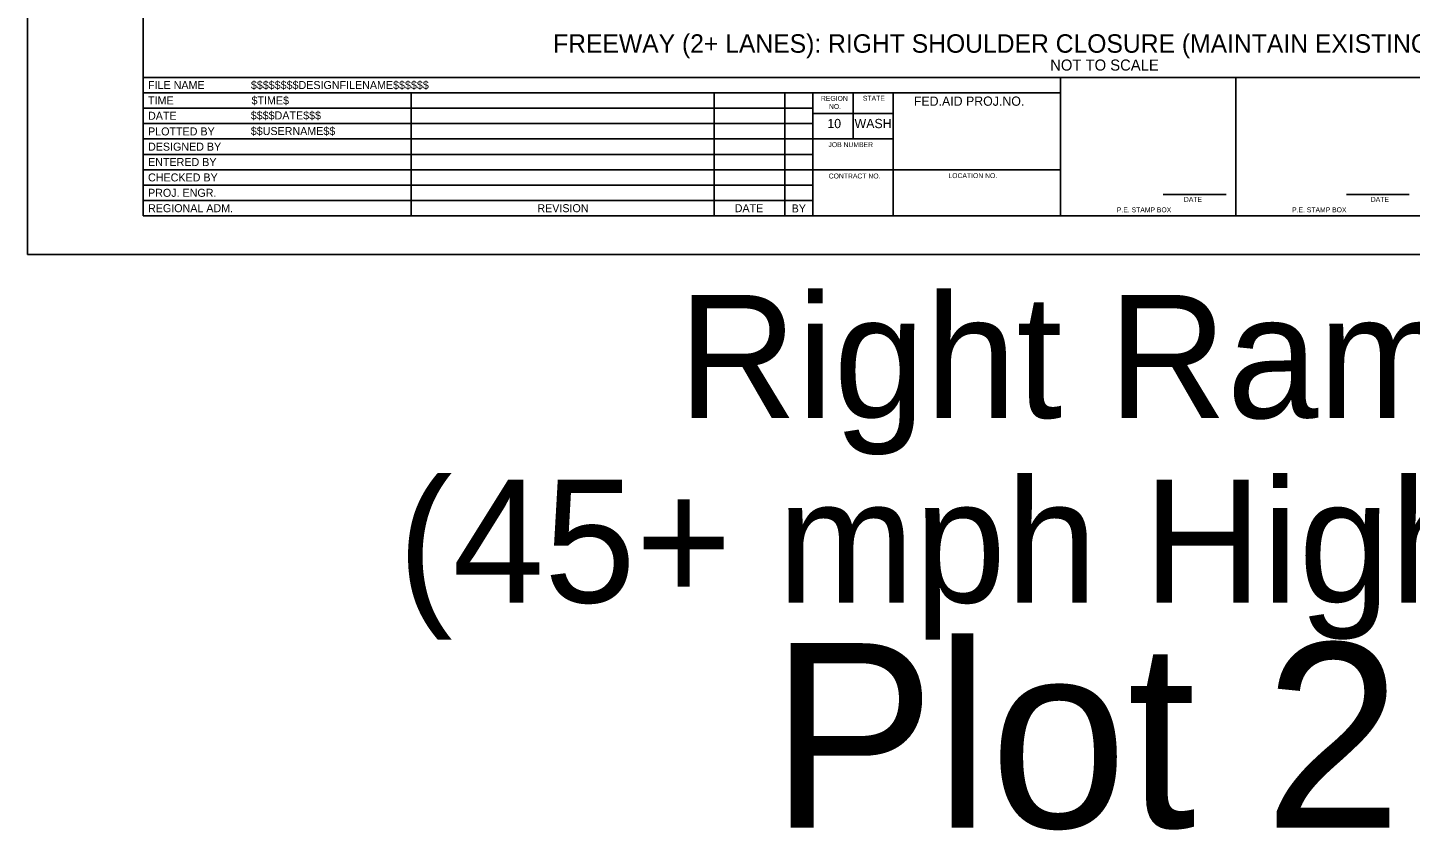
# Model space of a CAD drawing. Extents: x 99999.1 to 100055.7, y 99995 to 100013.2.
# Drawn here: x 100019.06 to 100030.3, y 99995.01 to 100001.53 of the extents above; entities that cross this region are included whole.
import ezdxf

# ---------------------------------------------------------------- set-up
doc = ezdxf.new("R2010")
doc.units = 0
for name, color, linetype in [('SH_DE_DetailHeading1Text', 7, 'Continuous'), ('SH_GI_PlotLimits', 7, 'Continuous'), ('SH_GI_SheetBorder', 7, 'Continuous'), ('SH_GI_SheetLocationText', 7, 'Continuous'), ('SH_GI_SheetTextInCells', 7, 'Continuous'), ('SH_GI_TitleBlockText', 7, 'Continuous')]:
    doc.layers.add(name, color=color, linetype=linetype)

msp = doc.modelspace()

# ---------------------------------------------------------------- linework, layer by layer
at = {"layer": 'SH_GI_PlotLimits'}
msp.add_lwpolyline([(100019.062, 99999.687), (100036.062, 99999.687), (100036.062, 100010.687), (100019.062, 100010.687)], close=True, dxfattribs=at)
at = {"layer": 'SH_GI_SheetBorder'}
for p, q in [((100020, 100010.375), (100020, 100000)), ((100020, 100001.126), (100035.75, 100001.126)), ((100027.457, 100000), (100027.457, 100001.126)), ((100028.883, 100000), (100028.883, 100001.126)), ((100020, 100001.001), (100027.457, 100001.001)), ((100022.179, 100001.001), (100022.179, 100000)), ((100024.641, 100001.001), (100024.641, 100000)), ((100025.216, 100001.001), (100025.216, 100000)), ((100025.445, 100001.001), (100025.445, 100000)), ((100025.772, 100000.625), (100025.772, 100001.001)), ((100026.096, 100000), (100026.096, 100001.001)), ((100020, 100000.876), (100022.182, 100000.876)), ((100022.182, 100000.876), (100025.447, 100000.876)), ((100026.096, 100000.831), (100025.447, 100000.831)), ((100020, 100000.751), (100022.182, 100000.751)), ((100022.182, 100000.751), (100025.447, 100000.751)), ((100020, 100000.625), (100025.447, 100000.625)), ((100026.096, 100000.625), (100025.447, 100000.625)), ((100020, 100000.5), (100025.447, 100000.5)), ((100020, 100000.375), (100025.447, 100000.375)), ((100027.457, 100000.375), (100025.447, 100000.375)), ((100020, 100000.25), (100025.447, 100000.25)), ((100020, 100000.125), (100025.447, 100000.125)), ((100028.29, 100000.173), (100028.802, 100000.173)), ((100029.78, 100000.173), (100030.291, 100000.173)), ((100020, 100000), (100035.75, 100000))]:
    msp.add_line(p, q, dxfattribs=at)

# ---------------------------------------------------------------- texts
at = {"layer": 'SH_DE_DetailHeading1Text'}
for s, height, p in [('FREEWAY (2+ LANES): RIGHT SHOULDER CLOSURE (MAINTAIN EXISTING SPEED LIMIT)', 0.15, (100023.333, 100001.326)), ('NOT TO SCALE', 0.09, (100027.373, 100001.181))]:
    msp.add_text(s, height=height, rotation=360, dxfattribs=at).set_placement(p)
at = {"layer": 'SH_GI_SheetLocationText'}
for s, height, p in [('Right Ramps', 1, (100024.35, 99998.357)), ('(45+ mph Highways)', 1, (100022.071, 99996.857)), ('Plot 2', 1.5, (100025.1, 99995.027))]:
    msp.add_text(s, height=height, dxfattribs=at).set_placement(p)
at = {"layer": 'SH_GI_SheetTextInCells'}
for s, height, p in [('FILE NAME', 0.0651, (100020.041, 100001.031)), ('TIME', 0.0651, (100020.041, 100000.906)), ('REGION', 0.04, (100025.51, 100000.935)), ('NO.', 0.04, (100025.575, 100000.869)), ('STATE', 0.04, (100025.851, 100000.936)), ('FED.AID PROJ.NO.', 0.07506, (100026.265, 100000.895)), ('DATE', 0.0651, (100020.041, 100000.781)), ('10', 0.0751, (100025.562, 100000.713)), ('WASH', 0.0751, (100025.783, 100000.713)), ('PLOTTED BY', 0.0651, (100020.041, 100000.654)), ('DESIGNED BY', 0.06505, (100020.041, 100000.53)), ('JOB NUMBER', 0.04, (100025.571, 100000.559)), ('ENTERED BY', 0.0651, (100020.041, 100000.405)), ('CHECKED BY', 0.0651, (100020.041, 100000.28)), ('CONTRACT NO.', 0.04003, (100025.573, 100000.304)), ('LOCATION NO.', 0.04003, (100026.546, 100000.307)), ('PROJ. ENGR.', 0.06505, (100020.041, 100000.155)), ('DATE', 0.04, (100028.46, 100000.114)), ('DATE', 0.04, (100029.979, 100000.114)), ('REGIONAL ADM.', 0.06505, (100020.041, 100000.03)), ('REVISION', 0.0651, (100023.205, 100000.03)), ('DATE', 0.0651, (100024.809, 100000.03)), ('BY', 0.0651, (100025.272, 100000.028)), ('P.E. STAMP BOX', 0.04003, (100027.915, 100000.029)), ('P.E. STAMP BOX', 0.04003, (100029.339, 100000.029))]:
    msp.add_text(s, height=height, dxfattribs=at).set_placement(p)
at = {"layer": 'SH_GI_TitleBlockText'}
for s, height, p in [('$$$$$$$$DESIGNFILENAME$$$$$$', 0.06505, (100020.877, 100001.031)), ('$TIME$', 0.0651, (100020.882, 100000.906)), ('$$$$DATE$$$', 0.06505, (100020.876, 100000.784)), ('$$USERNAME$$', 0.06505, (100020.876, 100000.657))]:
    msp.add_text(s, height=height, dxfattribs=at).set_placement(p)

doc.saveas('drawing.dxf')
